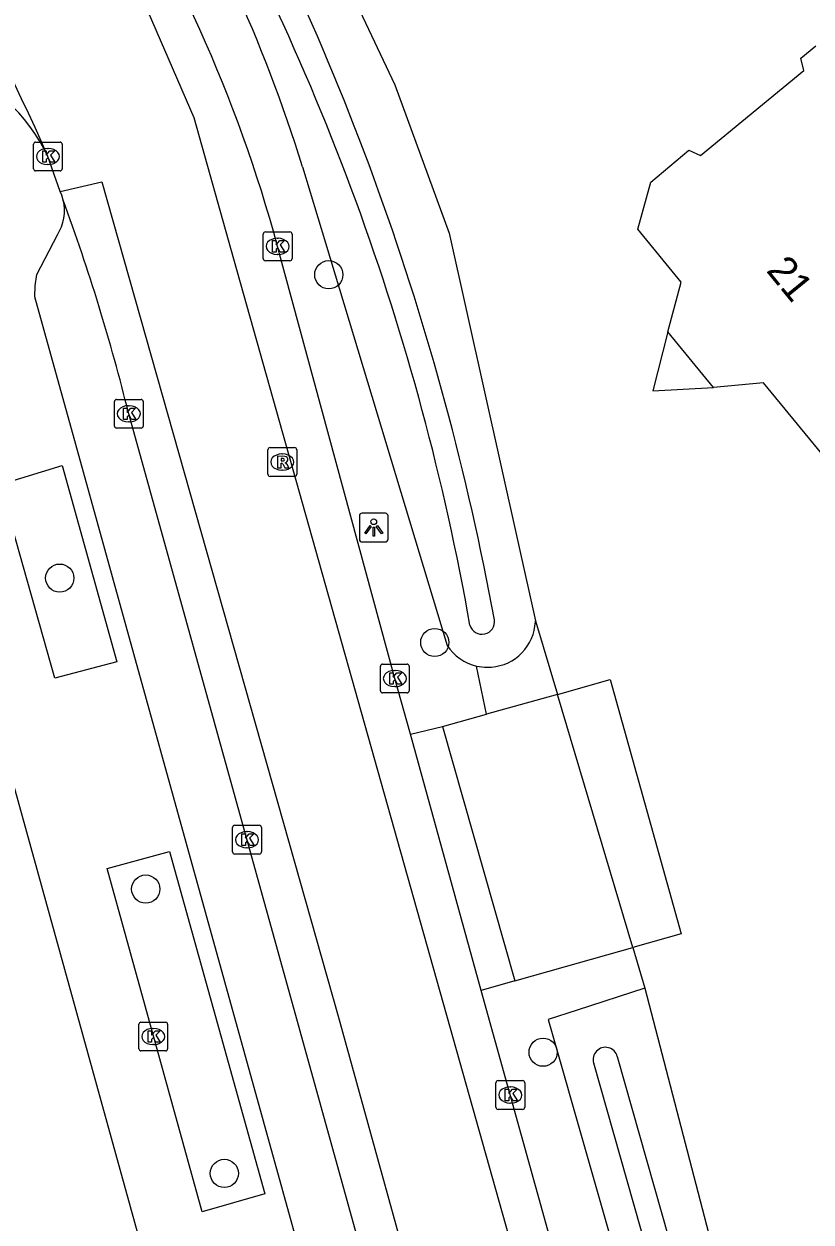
# Model space of a CAD drawing. Extents: x 163427 to 164190, y 380331 to 381641.
# Drawn here: x 163911 to 163938.33, y 381323.49 to 381365.11 of the extents above; entities that cross this region are included whole.
import ezdxf

# ---------------------------------------------------------------- set-up
doc = ezdxf.new("R2010")
doc.units = 0
for name, color, linetype in [('IMGEO_Boom', 7, 'Continuous'), ('IMGEO_Erf', 7, 'Continuous'), ('IMGEO_Groenvoorziening', 7, 'Continuous'), ('IMGEO_Kolk', 7, 'Continuous'), ('IMGEO_Lichtpunt', 7, 'Continuous'), ('IMGEO_Pand', 7, 'Continuous'), ('IMGEO_Pand_nummerreeks', 7, 'Continuous'), ('IMGEO_Pand_overbouw', 7, 'Continuous'), ('IMGEO_Rijbaan_lokaal_gesloten', 7, 'Continuous'), ('IMGEO_Rijbaan_lokaal_open', 7, 'Continuous'), ('IMGEO_Rioolput', 7, 'Continuous'), ('IMGEO_Voetpad_open', 7, 'Continuous'), ('IMGEO_Waterloop', 7, 'Continuous')]:
    doc.layers.add(name, color=color, linetype=linetype)

msp = doc.modelspace()

# ---------------------------------------------------------------- linework, layer by layer
at = {"layer": 'IMGEO_Boom'}
for centre in [(163921.582, 381356.4), (163912.239, 381345.86), (163925.262, 381343.624), (163915.225, 381335.058), (163929.024, 381329.389), (163917.955, 381325.179)]:
    msp.add_circle(centre, 0.489, dxfattribs=at)
at = {"layer": 'IMGEO_Erf'}
for points in [[(163917.715, 381374.256), (163918.762, 381372.692), (163921.534, 381367.958), (163923.872, 381362.995), (163925.758, 381357.843), (163928.758, 381344.373)], [(163932.56, 381331.611), (163942.876, 381291.921)]]:
    msp.add_lwpolyline(points, dxfattribs=at)
at = {"layer": 'IMGEO_Groenvoorziening'}
for points in [[(163920.674, 381360.154), (163921.471, 381357.514), (163925.693, 381343.522)], [(163927.084, 381342.761), (163927.233, 381342.767), (163927.381, 381342.786), (163927.526, 381342.819), (163927.668, 381342.864), (163927.806, 381342.922), (163927.937, 381342.991), (163928.062, 381343.073), (163928.18, 381343.165), (163928.288, 381343.267), (163928.387, 381343.378), (163928.476, 381343.498), (163928.553, 381343.626), (163928.619, 381343.759), (163928.673, 381343.898), (163928.714, 381344.042), (163928.742, 381344.188), (163928.756, 381344.337), (163928.758, 381344.373)], [(163928.758, 381344.373), (163929.518, 381341.822)], [(163927.062, 381341.135), (163926.711, 381342.805)], [(163932.138, 381333.029), (163932.56, 381331.611)], [(163932.56, 381331.611), (163930.201, 381330.848), (163929.201, 381330.524), (163940.334, 381291.493), (163941.561, 381291.7), (163942.876, 381291.921)]]:
    msp.add_lwpolyline(points, dxfattribs=at)
for centre, radius, start, end in [((163869.721, 381344.268), 53.372, 17.3163, 31.9027), ((163927.096, 381344.433), 1.673, 212.9934, 256.6908), ((163927.101, 381344.511), 1.75, 257.111, 269.4336)]:
    msp.add_arc(centre, radius, start, end, dxfattribs=at)
at = {"layer": 'IMGEO_Kolk'}
for p, q in [((163911.402, 381361.008), (163912.254, 381361.008)), ((163911.327, 381360.082), (163911.327, 381360.934)), ((163911.815, 381360.788), (163911.84, 381360.788)), ((163912.328, 381360.934), (163912.328, 381360.082)), ((163911.838, 381360.228), (163911.813, 381360.228)), ((163912.254, 381360.008), (163911.402, 381360.008)), ((163919.306, 381356.96), (163919.306, 381357.812)), ((163919.381, 381357.886), (163920.233, 381357.886)), ((163920.307, 381357.812), (163920.307, 381356.96)), ((163919.794, 381357.666), (163919.819, 381357.666)), ((163920.233, 381356.886), (163919.381, 381356.886)), ((163919.817, 381357.106), (163919.792, 381357.106)), ((163914.137, 381351.144), (163914.137, 381351.996)), ((163914.212, 381352.07), (163915.064, 381352.07)), ((163914.625, 381351.85), (163914.65, 381351.85)), ((163915.138, 381351.996), (163915.138, 381351.144)), ((163915.064, 381351.07), (163914.212, 381351.07)), ((163914.648, 381351.29), (163914.623, 381351.29)), ((163923.375, 381341.945), (163923.375, 381342.797)), ((163923.45, 381342.871), (163924.302, 381342.871)), ((163924.376, 381342.797), (163924.376, 381341.945)), ((163923.863, 381342.651), (163923.888, 381342.651)), ((163924.302, 381341.871), (163923.45, 381341.871)), ((163923.886, 381342.091), (163923.861, 381342.091)), ((163918.242, 381336.346), (163918.242, 381337.198)), ((163918.317, 381337.272), (163919.169, 381337.272)), ((163918.73, 381337.052), (163918.755, 381337.052)), ((163919.243, 381337.198), (163919.243, 381336.346)), ((163918.753, 381336.492), (163918.728, 381336.492)), ((163919.169, 381336.272), (163918.317, 381336.272)), ((163914.985, 381329.507), (163914.985, 381330.359)), ((163915.06, 381330.433), (163915.912, 381330.433)), ((163915.473, 381330.213), (163915.498, 381330.213)), ((163915.986, 381330.359), (163915.986, 381329.507)), ((163915.912, 381329.433), (163915.06, 381329.433)), ((163915.496, 381329.653), (163915.471, 381329.653)), ((163927.386, 381327.477), (163927.386, 381328.329)), ((163927.461, 381328.403), (163928.313, 381328.403)), ((163927.874, 381328.183), (163927.899, 381328.183)), ((163928.387, 381328.329), (163928.387, 381327.477)), ((163928.313, 381327.403), (163927.461, 381327.403)), ((163927.897, 381327.623), (163927.872, 381327.623))]:
    msp.add_line(p, q, dxfattribs=at)
for points in [[(163911.402, 381361.008), (163912.254, 381361.008)], [(163911.327, 381360.082), (163911.327, 381360.934)], [(163911.648, 381360.708), (163911.771, 381360.708), (163911.771, 381360.557), (163911.901, 381360.708), (163912.065, 381360.708), (163911.919, 381360.557), (163912.072, 381360.308), (163911.92, 381360.308), (163911.835, 381360.472), (163911.771, 381360.405), (163911.771, 381360.308), (163911.648, 381360.308), (163911.648, 381360.708)], [(163912.328, 381360.934), (163912.328, 381360.082)], [(163912.254, 381360.008), (163911.402, 381360.008)], [(163919.306, 381356.96), (163919.306, 381357.812)], [(163919.381, 381357.886), (163920.233, 381357.886)], [(163920.307, 381357.812), (163920.307, 381356.96)], [(163919.627, 381357.586), (163919.75, 381357.586), (163919.75, 381357.435), (163919.88, 381357.586), (163920.044, 381357.586), (163919.898, 381357.435), (163920.051, 381357.186), (163919.899, 381357.186), (163919.814, 381357.35), (163919.75, 381357.283), (163919.75, 381357.186), (163919.627, 381357.186), (163919.627, 381357.586)], [(163920.233, 381356.886), (163919.381, 381356.886)], [(163914.137, 381351.144), (163914.137, 381351.996)], [(163914.212, 381352.07), (163915.064, 381352.07)], [(163915.138, 381351.996), (163915.138, 381351.144)], [(163914.458, 381351.77), (163914.581, 381351.77), (163914.581, 381351.619), (163914.711, 381351.77), (163914.875, 381351.77), (163914.729, 381351.619), (163914.882, 381351.37), (163914.73, 381351.37), (163914.645, 381351.534), (163914.581, 381351.467), (163914.581, 381351.37), (163914.458, 381351.37), (163914.458, 381351.77)], [(163915.064, 381351.07), (163914.212, 381351.07)], [(163923.375, 381341.945), (163923.375, 381342.797)], [(163923.45, 381342.871), (163924.302, 381342.871)], [(163924.376, 381342.797), (163924.376, 381341.945)], [(163923.696, 381342.571), (163923.819, 381342.571), (163923.819, 381342.42), (163923.949, 381342.571), (163924.113, 381342.571), (163923.967, 381342.42), (163924.12, 381342.171), (163923.968, 381342.171), (163923.883, 381342.335), (163923.819, 381342.268), (163923.819, 381342.171), (163923.696, 381342.171), (163923.696, 381342.571)], [(163924.302, 381341.871), (163923.45, 381341.871)], [(163918.242, 381336.346), (163918.242, 381337.198)], [(163918.317, 381337.272), (163919.169, 381337.272)], [(163918.563, 381336.972), (163918.686, 381336.972), (163918.686, 381336.821), (163918.816, 381336.972), (163918.98, 381336.972), (163918.834, 381336.821), (163918.987, 381336.572), (163918.835, 381336.572), (163918.75, 381336.736), (163918.686, 381336.669), (163918.686, 381336.572), (163918.563, 381336.572), (163918.563, 381336.972)], [(163919.243, 381337.198), (163919.243, 381336.346)], [(163919.169, 381336.272), (163918.317, 381336.272)], [(163914.985, 381329.507), (163914.985, 381330.359)], [(163915.06, 381330.433), (163915.912, 381330.433)], [(163915.986, 381330.359), (163915.986, 381329.507)], [(163915.306, 381330.133), (163915.429, 381330.133), (163915.429, 381329.982), (163915.559, 381330.133), (163915.723, 381330.133), (163915.577, 381329.982), (163915.73, 381329.733), (163915.578, 381329.733), (163915.493, 381329.897), (163915.429, 381329.83), (163915.429, 381329.733), (163915.306, 381329.733), (163915.306, 381330.133)], [(163915.912, 381329.433), (163915.06, 381329.433)], [(163927.386, 381327.477), (163927.386, 381328.329)], [(163927.461, 381328.403), (163928.313, 381328.403)], [(163928.387, 381328.329), (163928.387, 381327.477)], [(163927.707, 381328.103), (163927.83, 381328.103), (163927.83, 381327.952), (163927.96, 381328.103), (163928.124, 381328.103), (163927.978, 381327.952), (163928.131, 381327.703), (163927.979, 381327.703), (163927.894, 381327.867), (163927.83, 381327.8), (163927.83, 381327.703), (163927.707, 381327.703), (163927.707, 381328.103)], [(163928.313, 381327.403), (163927.461, 381327.403)]]:
    msp.add_lwpolyline(points, dxfattribs=at)
for centre, start, end in [((163911.404, 381360.932), 91.552, 178.448), ((163911.404, 381360.932), 91.552, 178.448), ((163912.252, 381360.932), 1.552, 88.448), ((163912.252, 381360.932), 1.552, 88.448), ((163911.404, 381360.084), 181.552, 268.448), ((163911.404, 381360.084), 181.552, 268.448), ((163912.252, 381360.084), 271.552, 358.448), ((163912.252, 381360.084), 271.552, 358.448), ((163919.383, 381357.81), 91.552, 178.448), ((163919.383, 381357.81), 91.552, 178.448), ((163920.231, 381357.81), 1.552, 88.448), ((163920.231, 381357.81), 1.552, 88.448), ((163919.383, 381356.962), 181.552, 268.448), ((163919.383, 381356.962), 181.552, 268.448), ((163920.231, 381356.962), 271.552, 358.448), ((163920.231, 381356.962), 271.552, 358.448), ((163914.214, 381351.994), 91.552, 178.448), ((163914.214, 381351.994), 91.552, 178.448), ((163915.062, 381351.994), 1.552, 88.448), ((163915.062, 381351.994), 1.552, 88.448), ((163914.214, 381351.146), 181.552, 268.448), ((163914.214, 381351.146), 181.552, 268.448), ((163915.062, 381351.146), 271.552, 358.448), ((163915.062, 381351.146), 271.552, 358.448), ((163923.452, 381342.795), 91.552, 178.448), ((163923.452, 381342.795), 91.552, 178.448), ((163924.3, 381342.795), 1.552, 88.448), ((163924.3, 381342.795), 1.552, 88.448), ((163923.452, 381341.947), 181.552, 268.448), ((163923.452, 381341.947), 181.552, 268.448), ((163924.3, 381341.947), 271.552, 358.448), ((163924.3, 381341.947), 271.552, 358.448), ((163918.319, 381337.196), 91.552, 178.448), ((163918.319, 381337.196), 91.552, 178.448), ((163919.167, 381337.196), 1.552, 88.448), ((163919.167, 381337.196), 1.552, 88.448), ((163918.319, 381336.348), 181.552, 268.448), ((163918.319, 381336.348), 181.552, 268.448), ((163919.167, 381336.348), 271.552, 358.448), ((163919.167, 381336.348), 271.552, 358.448), ((163915.062, 381330.357), 91.552, 178.448), ((163915.062, 381330.357), 91.552, 178.448), ((163915.91, 381330.357), 1.552, 88.448), ((163915.91, 381330.357), 1.552, 88.448), ((163915.062, 381329.509), 181.552, 268.448), ((163915.062, 381329.509), 181.552, 268.448), ((163915.91, 381329.509), 271.552, 358.448), ((163915.91, 381329.509), 271.552, 358.448), ((163927.463, 381328.327), 91.552, 178.448), ((163927.463, 381328.327), 91.552, 178.448), ((163928.311, 381328.327), 1.552, 88.448), ((163928.311, 381328.327), 1.552, 88.448), ((163927.463, 381327.479), 181.552, 268.448), ((163927.463, 381327.479), 181.552, 268.448), ((163928.311, 381327.479), 271.552, 358.448), ((163928.311, 381327.479), 271.552, 358.448)]:
    msp.add_arc(centre, 0.0765, start, end, dxfattribs=at)
for centre, major_axis, ratio, start_param, end_param in [((163911.814, 381360.508), (-0.387, 0.002), 0.722429, 4.712389, 7.853982), ((163911.839, 381360.508), (-0.39, 0.002), 0.717154, 1.570796, 4.712389), ((163919.793, 381357.386), (-0.387, 0.002), 0.722429, 4.712389, 7.853982), ((163919.818, 381357.386), (-0.39, 0.002), 0.717154, 1.570796, 4.712389), ((163914.624, 381351.57), (-0.387, 0.002), 0.722429, 4.712389, 7.853982), ((163914.649, 381351.57), (-0.39, 0.002), 0.717154, 1.570796, 4.712389), ((163923.862, 381342.371), (-0.387, 0.002), 0.722429, 4.712389, 7.853982), ((163923.887, 381342.371), (-0.39, 0.002), 0.717154, 1.570796, 4.712389), ((163918.729, 381336.772), (-0.387, 0.002), 0.722429, 4.712389, 7.853982), ((163918.754, 381336.772), (-0.39, 0.002), 0.717154, 1.570796, 4.712389), ((163915.472, 381329.933), (-0.387, 0.002), 0.722429, 4.712389, 7.853982), ((163915.497, 381329.933), (-0.39, 0.002), 0.717154, 1.570796, 4.712389), ((163927.873, 381327.903), (-0.387, 0.002), 0.722429, 4.712389, 7.853982), ((163927.898, 381327.903), (-0.39, 0.002), 0.717154, 1.570796, 4.712389)]:
    msp.add_ellipse(centre, major_axis=major_axis, ratio=ratio, start_param=start_param, end_param=end_param, dxfattribs=at)
at = {"layer": 'IMGEO_Lichtpunt'}
for p, q in [((163923.546, 381348.115), (163922.738, 381348.115)), ((163923.546, 381348.115), (163922.738, 381348.115)), ((163922.644, 381348.02), (163922.644, 381347.213)), ((163922.644, 381348.02), (163922.644, 381347.213)), ((163923.64, 381347.213), (163923.64, 381348.02)), ((163923.64, 381347.213), (163923.64, 381348.02)), ((163922.738, 381347.119), (163923.546, 381347.119)), ((163922.738, 381347.119), (163923.546, 381347.119))]:
    msp.add_line(p, q, dxfattribs=at)
for points in [[(163923.018, 381347.684), (163923.057, 381347.656), (163922.869, 381347.394), (163922.831, 381347.421), (163923.018, 381347.684)], [(163923.23, 381347.656), (163923.268, 381347.683), (163923.455, 381347.421), (163923.416, 381347.393), (163923.23, 381347.656)], [(163923.12, 381347.636), (163923.167, 381347.636), (163923.167, 381347.314), (163923.12, 381347.314), (163923.12, 381347.636)]]:
    msp.add_lwpolyline(points, dxfattribs=at)
msp.add_circle((163923.143, 381347.818), 0.0994, dxfattribs=at)
for centre, start, end in [((163922.738, 381348.02), 90, 180), ((163922.738, 381348.02), 90, 180), ((163923.546, 381348.02), 0, 90), ((163923.546, 381348.02), 0, 90), ((163922.738, 381347.213), 180, 270), ((163922.738, 381347.213), 180, 270), ((163923.546, 381347.213), 270, 0), ((163923.546, 381347.213), 270, 360)]:
    msp.add_arc(centre, 0.0946, start, end, dxfattribs=at)
at = {"layer": 'IMGEO_Pand'}
msp.add_lwpolyline([(163940.156, 381348.411), (163936.678, 381352.639), (163934.94, 381352.485), (163933.359, 381354.422), (163933.819, 381356.138), (163932.31, 381357.978), (163932.769, 381359.621), (163934.084, 381360.723), (163934.486, 381360.538), (163938.074, 381363.494), (163937.972, 381363.929), (163938.489, 381364.355)], dxfattribs=at)
at = {"layer": 'IMGEO_Pand_overbouw'}
msp.add_lwpolyline([(163934.94, 381352.485), (163933.359, 381354.422), (163932.83, 381352.371)], close=True, dxfattribs=at)
at = {"layer": 'IMGEO_Rijbaan_lokaal_gesloten'}
for points in [[(163841.848, 381430.533), (163854.116, 381421.564), (163876.198, 381404.193), (163879.891, 381401.183), (163901.267, 381383.762), (163907.4, 381377.437), (163911.836, 381371.772), (163914.855, 381366.58), (163916.89, 381361.86), (163918.27, 381356.954), (163928.731, 381319.775), (163929.065, 381319.87), (163929.681, 381317.703), (163929.322, 381317.601), (163935.871, 381293.48), (163936.342, 381291.876), (163937.807, 381292.203)], [(163912.249, 381359.295), (163911.825, 381360.508)], [(163912.249, 381359.295), (163913.697, 381359.629), (163921.907, 381330.645), (163925.185, 381318.778), (163924.817, 381318.679), (163925.405, 381316.489), (163925.802, 381316.596), (163930.68, 381299.334), (163933.228, 381290.176), (163942.098, 381254.961), (163943.722, 381247.313), (163943.287, 381247.227), (163943.726, 381245.01), (163944.183, 381245.1), (163944.552, 381243.335), (163946.144, 381233.78), (163948.882, 381217.269), (163947.265, 381217.038)], [(163912.358, 381358.996), (163912.307, 381359.162), (163912.249, 381359.295)], [(163924.423, 381340.435), (163923.875, 381342.371), (163919.806, 381357.386)], [(163930.967, 381292.691), (163914.635, 381351.57)], [(163926.876, 381331.531), (163924.423, 381340.435)], [(163937.807, 381292.203), (163937.102, 381294.734), (163926.876, 381331.531)]]:
    msp.add_lwpolyline(points, dxfattribs=at)
for centre, radius, start, end in [((163861.382, 381338.888), 54.881, 23.2004, 41.5796), ((163870.916, 381344.1), 50.663, 15.2029, 33.3278), ((163845.611, 381334.468), 71.111, 13.91619, 20.17755)]:
    msp.add_arc(centre, radius, start, end, dxfattribs=at)
at = {"layer": 'IMGEO_Rijbaan_lokaal_open'}
msp.add_arc((163906.395, 381357.979), 5.99, 24.9731, 117.8774, dxfattribs=at)
at = {"layer": 'IMGEO_Rioolput'}
for p, q in [((163919.466, 381349.467), (163919.466, 381350.319)), ((163919.541, 381350.393), (163920.393, 381350.393)), ((163920.467, 381350.319), (163920.467, 381349.467)), ((163919.954, 381350.173), (163919.979, 381350.173)), ((163920.393, 381349.393), (163919.541, 381349.393)), ((163919.977, 381349.613), (163919.952, 381349.613))]:
    msp.add_line(p, q, dxfattribs=at)
for points in [[(163919.466, 381349.467), (163919.466, 381350.319)], [(163919.541, 381350.393), (163920.393, 381350.393)], [(163920.467, 381350.319), (163920.467, 381349.467)], [(163920.055, 381350.091), (163919.803, 381350.093), (163919.803, 381349.693)], [(163919.803, 381349.693), (163919.927, 381349.693), (163919.927, 381349.855), (163919.938, 381349.855)], [(163919.981, 381350.012), (163919.927, 381350.012), (163919.927, 381349.931)], [(163919.927, 381349.931), (163919.979, 381349.931)], [(163919.985, 381349.826), (163920.056, 381349.693), (163920.196, 381349.693), (163920.131, 381349.819)], [(163920.393, 381349.393), (163919.541, 381349.393)]]:
    msp.add_lwpolyline(points, dxfattribs=at)
for centre, radius, start, end in [((163919.543, 381350.317), 0.0765, 91.552, 178.448), ((163919.543, 381350.317), 0.0765, 91.552, 178.448), ((163920.391, 381350.317), 0.0765, 1.552, 88.448), ((163920.391, 381350.317), 0.0765, 1.552, 88.448), ((163919.937, 381349.802), 0.0533, 26.0293, 88.6989), ((163919.963, 381350.12), 0.19, 274.7715, 282.9687), ((163919.987, 381349.916), 0.0964, 77.0061, 93.1865), ((163920.001, 381349.973), 0.0378, 276.6634, 79.6772), ((163920.054, 381349.981), 0.109, 350.3612, 89.416), ((163920.052, 381349.981), 0.112, 277.5842, 350.9817), ((163920.036, 381349.766), 0.108, 29.5134, 73.7905), ((163919.543, 381349.469), 0.0765, 181.552, 268.448), ((163919.543, 381349.469), 0.0765, 181.552, 268.448), ((163920.391, 381349.469), 0.0765, 271.552, 358.448), ((163920.391, 381349.469), 0.0765, 271.552, 358.448)]:
    msp.add_arc(centre, radius, start, end, dxfattribs=at)
for centre, major_axis, ratio, start_param, end_param in [((163919.953, 381349.893), (-0.387, 0.002), 0.722429, 4.712389, 7.853982), ((163919.978, 381349.893), (-0.39, 0.002), 0.717154, 1.570796, 4.712389)]:
    msp.add_ellipse(centre, major_axis=major_axis, ratio=ratio, start_param=start_param, end_param=end_param, dxfattribs=at)
at = {"layer": 'IMGEO_Voetpad_open'}
for points in [[(163905.25, 381358.102), (163926.328, 381281.925)], [(163921.4, 381319.482), (163919.989, 381324.572), (163916.635, 381336.671), (163914.816, 381343.233), (163912.802, 381350.5), (163911.38, 381355.63), (163911.39, 381356.014), (163911.449, 381356.413), (163912.156, 381357.786)], [(163912.068, 381342.379), (163910.162, 381349.117), (163912.328, 381349.775), (163914.224, 381342.952), (163912.068, 381342.379)], [(163929.518, 381341.822), (163931.347, 381342.333), (163933.816, 381333.507), (163932.138, 381333.029)], [(163929.518, 381341.822), (163927.479, 381341.252), (163927.062, 381341.135)], [(163932.138, 381333.029), (163929.518, 381341.822)], [(163925.532, 381340.708), (163927.062, 381341.135)], [(163924.423, 381340.435), (163925.532, 381340.708)], [(163925.532, 381340.708), (163928.044, 381331.864)], [(163919.357, 381324.464), (163917.181, 381323.846), (163913.884, 381335.777), (163916.055, 381336.36), (163919.357, 381324.464)], [(163928.044, 381331.864), (163929.804, 381332.365), (163932.138, 381333.029)], [(163928.044, 381331.864), (163926.876, 381331.531)]]:
    msp.add_lwpolyline(points, dxfattribs=at)
msp.add_arc((163910.856, 381358.625), 1.547, 327.171, 13.8736, dxfattribs=at)
at = {"layer": 'IMGEO_Waterloop'}
msp.add_lwpolyline([(163931.599, 381329.241), (163941.823, 381293.174), (163941.022, 381292.928), (163930.78, 381329.005)], dxfattribs=at)
for centre, radius, start, end in [((163834.42, 381327.311), 94.475, 10.42804, 29.1648), ((163841.503, 381329.282), 86.284, 9.97217, 30.24706), ((163926.902, 381344.348), 0.437, 196.4882, 8.2702), ((163931.186, 381329.134), 0.426, 14.5133, 197.6361)]:
    msp.add_arc(centre, radius, start, end, dxfattribs=at)

# ---------------------------------------------------------------- texts
at = {"layer": 'IMGEO_Pand_nummerreeks'}
msp.add_text('21', height=1, rotation=309.2519, dxfattribs=at).set_placement((163936.748, 381356.535))

doc.saveas('drawing.dxf')
